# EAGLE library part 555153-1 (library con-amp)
AMP connector
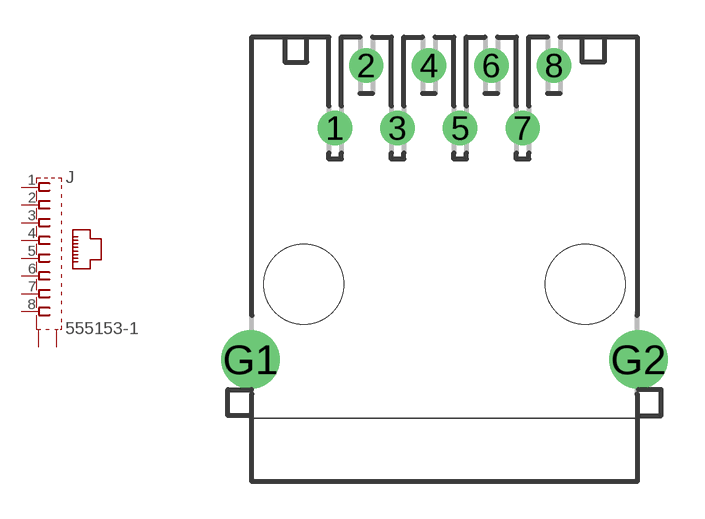
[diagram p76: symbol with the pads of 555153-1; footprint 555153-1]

Designator prefix J

## 555153-1 (MF: TYCO ELECTRONICS; MPN: 5555153-1; OC_FARNELL: 1557072; OC_NEWARK: 42K8753)  [555153-1]
1  1  pas
2  2  pas
3  3  pas
4  4  pas
5  5  pas
6  6  pas
7  7  pas
8  8  pas
G1  S1  pas
G2  S2  pas

## Footprint 555153-1 (pad centres in mm)
Modular Jack PC Board Ground
drill 0.889 round: 1 -4.445,6.35; 2 -3.175,8.89; 3 -1.905,6.35; 4 -0.635,8.89; 5 0.635,6.35; 6 1.905,8.89; 7 3.175,6.35; 8 4.445,8.89
drill 1.575 pad 2.184 round: G1 -7.874,-3.048; G2 7.874,-3.048
hole 3.251 at -5.715,0
hole 3.251 at 5.715,0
